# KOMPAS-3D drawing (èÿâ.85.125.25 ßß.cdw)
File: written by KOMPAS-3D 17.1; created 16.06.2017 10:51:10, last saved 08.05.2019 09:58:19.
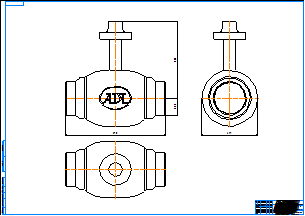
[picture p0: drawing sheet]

Sheet 1: A0, landscape

Title block, sheet 1: name: КШГ.85.125.25 сс; material: Внимание! Данный продукт является объектом авторского права ООО «Торговый Дом АДЛ». / Запрещается изменение, копирование, распространение / (в том числе путем копирования на другие сайты и ресурсы в Интернете) / или любое иное использование информации и объектов без предварительного / согласия правообладателя (ООО «Торговый Дом АДЛ»).; scale: 1:1; sheets: 1; organisation: ООО "Торговый дом АДЛ"; sheet format: A0; stored path: C:\Users\tra\Desktop\2д чертежи\Шаровые краны БИВАЛ\КШ_Бивал_серия_82_85\KOMPAS 2D\КШГ.85.125.25 сс.cdw

Views: Спереди 1, Проекционный вид 2, Проекционный вид 3
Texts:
  Klimkovich
  ADL
Dimensions and other numbers on the sheet: 390; 300; 66,5; 219; 1:1; 1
